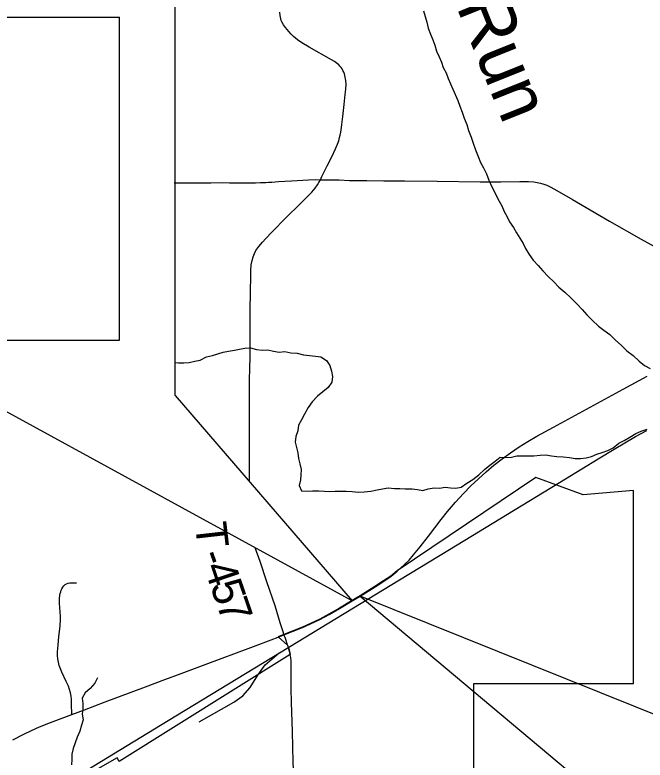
# Model space of a CAD drawing. Extents: x 0 to 34, y 0 to 22.
# Drawn here: x 4.117 to 5.253, y 16.828 to 18.172 of the extents above; entities that cross this region are included whole.
import ezdxf

# ---------------------------------------------------------------- set-up
doc = ezdxf.new("R2010")
doc.units = 0
for name, color, linetype in [('GM_X_County_Road', 7, 'Continuous'), ('GM_X_County_Road_Text', 7, 'Continuous'), ('GM_X_County_Text', 7, 'Continuous'), ('GM_X_Interchange_Ramps', 7, 'Continuous'), ('GM_X_State_Route', 7, 'Continuous'), ('GM_X_Township_Road_Text', 7, 'Continuous'), ('GM_X_Township_Text', 7, 'Continuous'), ('SH_Text', 7, 'Continuous')]:
    doc.layers.add(name, color=color, linetype=linetype)

msp = doc.modelspace()

# ---------------------------------------------------------------- linework, layer by layer
at = {"layer": 'GM_X_County_Road'}
for points in [[(4.8065, 17.1688), (4.8197, 17.1807), (4.8277, 17.1889), (4.836, 17.1981), (4.8477, 17.2126), (4.8629, 17.2322), (4.8854, 17.262), (4.8971, 17.2766), (4.9113, 17.2931), (4.926, 17.3091), (4.9391, 17.3225), (4.9527, 17.3353), (4.9666, 17.3478), (4.9809, 17.3598), (4.9956, 17.3713), (5.0107, 17.3823), (5.0261, 17.3928), (5.0419, 17.4028), (5.058, 17.4123), (5.088, 17.4288), (5.2137, 17.4969), (5.2573, 17.5207)], [(4.5916, 17.05), (4.6021, 17.0542), (4.6357, 17.0673), (4.65, 17.0736), (4.6668, 17.0818), (4.6834, 17.0905), (4.7023, 17.1014), (4.7253, 17.1152), (4.7398, 17.1239), (4.7664, 17.1403), (4.7821, 17.1505), (4.7949, 17.1595), (4.7989, 17.1626), (4.8065, 17.1688)], [(4.1131, 16.8647), (4.1328, 16.8749), (4.1468, 16.8816), (4.1611, 16.8878), (4.1813, 16.8958), (4.2194, 16.9103), (4.2422, 16.9189), (4.2799, 16.9331), (4.3525, 16.9603), (4.3874, 16.9733), (4.4164, 16.9843), (4.46, 17.0006), (4.5471, 17.0332), (4.5791, 17.0452), (4.5916, 17.05)]]:
    msp.add_lwpolyline(points, dxfattribs=at)
at = {"layer": 'GM_X_County_Road_Text'}
for points in [[(4.8535, 18.1796), (4.8568, 18.1693), (4.8597, 18.159), (4.8623, 18.148), (4.8664, 18.1374), (4.8708, 18.1271), (4.8742, 18.1172), (4.8771, 18.1065), (4.882, 18.0963), (4.8864, 18.0867), (4.8894, 18.0772), (4.8946, 18.0673), (4.8983, 18.0571), (4.9065, 18.038), (4.9154, 18.0175), (4.9195, 18.0076), (4.9236, 17.9965), (4.9269, 17.9855), (4.9321, 17.9741), (4.9347, 17.9634), (4.9399, 17.9513), (4.9436, 17.9406), (4.9477, 17.9288), (4.9521, 17.9166), (4.9566, 17.9056), (4.9618, 17.8961), (4.9674, 17.8854), (4.9718, 17.874), (4.9771, 17.8618), (4.9823, 17.8519), (4.9879, 17.8405), (4.995, 17.8275), (4.9994, 17.8176), (5.0047, 17.8081), (5.0091, 17.7986), (5.0159, 17.7886), (5.0215, 17.7791), (5.0278, 17.7696), (5.0338, 17.76), (5.0379, 17.7505), (5.0443, 17.7398), (5.0514, 17.7295), (5.0608, 17.72), (5.069, 17.7104), (5.0788, 17.7005), (5.0886, 17.6909)], [(5.0886, 17.6909), (5.0976, 17.681), (5.1085, 17.6721), (5.1198, 17.6614), (5.1311, 17.6503), (5.1401, 17.6408), (5.1484, 17.6308), (5.1581, 17.6213), (5.1694, 17.6109), (5.1792, 17.6036), (5.1901, 17.5956), (5.2003, 17.5852), (5.2101, 17.5764), (5.2206, 17.5661), (5.2319, 17.5576), (5.2428, 17.5477), (5.2526, 17.54), (5.2624, 17.5342)], [(4.4056, 17.5451), (4.4119, 17.5446), (4.4214, 17.5445), (4.4309, 17.5452), (4.4412, 17.5477), (4.451, 17.5495), (4.4621, 17.5551), (4.4731, 17.558), (4.483, 17.561), (4.4925, 17.5636), (4.5023, 17.5654), (4.5126, 17.5672), (4.5221, 17.5694), (4.5316, 17.5712), (4.5418, 17.5715), (4.5528, 17.5687), (4.563, 17.5675), (4.5732, 17.5678), (4.5831, 17.5658), (4.5933, 17.5638), (4.6039, 17.5648), (4.6145, 17.5625), (4.6262, 17.562), (4.6376, 17.5588), (4.6482, 17.558), (4.6588, 17.5564), (4.6686, 17.5551), (4.6788, 17.549), (4.6848, 17.5395), (4.6881, 17.5292), (4.6899, 17.5197), (4.6883, 17.5098), (4.6818, 17.5), (4.6719, 17.4925), (4.6624, 17.4843), (4.6532, 17.4741), (4.6459, 17.464), (4.639, 17.4519), (4.6336, 17.4417), (4.6286, 17.4319), (4.627, 17.422), (4.6235, 17.4118), (4.6223, 17.4016), (4.6248, 17.3917), (4.627, 17.3822), (4.6281, 17.3723), (4.631, 17.3625), (4.6332, 17.3522), (4.6328, 17.3427), (4.6319, 17.3333), (4.6296, 17.3234), (4.634, 17.3139), (4.6443, 17.313), (4.6538, 17.3137), (4.6651, 17.3136), (4.675, 17.3131), (4.6844, 17.3127), (4.6947, 17.313), (4.7144, 17.3128), (4.7254, 17.3123), (4.736, 17.3111), (4.7466, 17.3121), (4.7587, 17.3128), (4.7701, 17.3153), (4.7796, 17.3171), (4.7902, 17.3189), (4.8016, 17.3181), (4.8111, 17.318), (4.8206, 17.3175), (4.8331, 17.3174), (4.8429, 17.3162), (4.8527, 17.3142), (4.8622, 17.3171)], [(4.8622, 17.3171), (4.8729, 17.3193), (4.8827, 17.3185), (4.8926, 17.3203), (4.9024, 17.3191), (4.9119, 17.3186), (4.9214, 17.3204), (4.9317, 17.3275), (4.9427, 17.3339), (4.9538, 17.3425), (4.9637, 17.3522), (4.9733, 17.3601), (4.9828, 17.3672), (4.9923, 17.3747), (5.0026, 17.3739), (5.0124, 17.3746), (5.0219, 17.3767), (5.0322, 17.3767), (5.0435, 17.3769), (5.053, 17.3768), (5.0644, 17.3783), (5.0746, 17.3789), (5.0845, 17.3769), (5.0943, 17.3757), (5.1057, 17.3752), (5.117, 17.374), (5.1273, 17.372), (5.1371, 17.3719), (5.147, 17.3733), (5.1569, 17.3755), (5.1664, 17.3796), (5.1759, 17.3826), (5.1861, 17.3866), (5.196, 17.3911), (5.2059, 17.3994), (5.2155, 17.4042), (5.2257, 17.4102), (5.2368, 17.4173), (5.2463, 17.4214), (5.2569, 17.4247)], [(4.2659, 16.9767), (4.2609, 16.9669), (4.2528, 16.9571), (4.2433, 16.9496), (4.2379, 16.9398), (4.2393, 16.9303), (4.2393, 16.9208), (4.2384, 16.9109), (4.2398, 16.9007), (4.2367, 16.8909), (4.234, 16.8803), (4.2294, 16.8697), (4.2255, 16.8595), (4.2216, 16.8489), (4.2192, 16.8391), (4.2192, 16.8292), (4.2191, 16.8197)]]:
    msp.add_lwpolyline(points, dxfattribs=at)
at = {"layer": 'GM_X_County_Text'}
for points in [[(4.185, 16.7727), (4.3934, 16.8994), (4.6106, 17.0317), (4.8107, 17.1533), (4.9005, 17.208), (5.1096, 17.3353), (5.1688, 17.3712), (5.1978, 17.3889), (5.236, 17.4114), (5.2564, 17.4226)], [(4.4493, 16.8974), (4.5114, 16.9327), (4.5279, 16.9439), (4.5413, 16.9589), (4.5548, 16.9814), (4.5682, 17.0001), (4.5935, 17.0213)]]:
    msp.add_lwpolyline(points, dxfattribs=at)
at = {"layer": 'GM_X_Interchange_Ramps'}
for points in [[(4.668, 17.8748), (4.6706, 17.8803), (4.6737, 17.8868), (4.6801, 17.8996), (4.6887, 17.9162), (4.6952, 17.9303), (4.6988, 17.9389), (4.7008, 17.9449), (4.7024, 17.951), (4.7034, 17.9549), (4.7044, 17.9603), (4.7057, 17.9691), (4.7063, 17.9743), (4.708, 17.9889), (4.7104, 18.0105), (4.7126, 18.0286), (4.7136, 18.0379), (4.714, 18.0473), (4.7137, 18.0536), (4.7127, 18.0599), (4.712, 18.063), (4.7111, 18.066), (4.7099, 18.0689), (4.7084, 18.0718), (4.7068, 18.0745), (4.705, 18.0771), (4.703, 18.0795), (4.7008, 18.0818), (4.6984, 18.0839), (4.6934, 18.0877), (4.6881, 18.0911), (4.6473, 18.1139), (4.6341, 18.1219), (4.6265, 18.1272), (4.6193, 18.133), (4.6149, 18.1373), (4.6107, 18.1418), (4.6049, 18.149), (4.6014, 18.1541), (4.5984, 18.1594), (4.5973, 18.1621), (4.5963, 18.1647), (4.5956, 18.168), (4.5951, 18.171), (4.5945, 18.1771)], [(4.5397, 17.3302), (4.5398, 17.3387), (4.5399, 17.3625), (4.5399, 17.4012), (4.5399, 17.4851), (4.5402, 17.5126), (4.5406, 17.5354), (4.5409, 17.5541), (4.5409, 17.5649), (4.5409, 17.5958), (4.5413, 17.6349), (4.5416, 17.676), (4.5421, 17.6976), (4.5424, 17.7109), (4.5432, 17.7211), (4.5448, 17.7288), (4.5466, 17.7356), (4.5488, 17.7418), (4.5515, 17.747), (4.5568, 17.7545), (4.5634, 17.7619), (4.5694, 17.769), (4.58, 17.7803), (4.6063, 17.8067), (4.6306, 17.8307), (4.6439, 17.8437), (4.6524, 17.8526), (4.6584, 17.8598), (4.6626, 17.8658), (4.665, 17.8697), (4.668, 17.8748)], [(4.5741, 17.8701), (4.5801, 17.8705), (4.5921, 17.8713), (4.6039, 17.8722), (4.6154, 17.873), (4.6461, 17.8744), (4.6584, 17.8749), (4.668, 17.8748)], [(4.668, 17.8748), (4.6729, 17.8748), (4.6841, 17.8746), (4.7014, 17.8743), (4.7202, 17.8736), (4.7242, 17.8736)], [(4.7242, 17.8736), (4.7513, 17.8735), (4.7823, 17.8729), (4.8196, 17.8727), (4.8786, 17.872), (4.9562, 17.8712), (4.9935, 17.8711), (5.0277, 17.8715), (5.0432, 17.8713), (5.0525, 17.8708), (5.0586, 17.87), (5.0647, 17.8687), (5.0707, 17.867), (5.0764, 17.8647), (5.082, 17.862), (5.0902, 17.8576), (5.1225, 17.8389), (5.1544, 17.8202), (5.1895, 17.8002), (5.2461, 17.7678), (5.2814, 17.7482), (5.2916, 17.7428)], [(4.4043, 17.8692), (4.4234, 17.8693), (4.4452, 17.8693), (4.47, 17.8694), (4.4917, 17.8695), (4.5041, 17.8693), (4.5288, 17.8693), (4.5412, 17.8693), (4.5505, 17.8694), (4.5598, 17.8695), (4.5691, 17.8698), (4.5741, 17.8701)], [(4.6021, 17.0542), (4.601, 17.0578), (4.5952, 17.0758), (4.586, 17.1063), (4.5714, 17.1495), (4.5592, 17.1862), (4.5499, 17.211)], [(4.2194, 16.9103), (4.2192, 16.9153), (4.2189, 16.9246), (4.2186, 16.9371), (4.218, 16.9433), (4.2169, 16.9495), (4.2154, 16.9555), (4.2132, 16.9614), (4.2094, 16.9699), (4.2013, 16.9868), (4.1989, 16.9926), (4.1968, 16.9985), (4.1953, 17.0045), (4.1943, 17.0107), (4.1938, 17.0169), (4.1939, 17.0231), (4.1948, 17.0356), (4.1963, 17.0511), (4.1982, 17.0697), (4.1992, 17.0821), (4.1992, 17.0883), (4.1987, 17.0944), (4.1976, 17.1036), (4.1973, 17.1098), (4.1974, 17.1192), (4.198, 17.1253), (4.1986, 17.1284), (4.1994, 17.1314), (4.2004, 17.1344), (4.2017, 17.1372), (4.2032, 17.1399), (4.2051, 17.1424), (4.2073, 17.1445), (4.2099, 17.1461), (4.2128, 17.1471), (4.2159, 17.1476), (4.2189, 17.1478), (4.222, 17.1478), (4.2277, 17.1477)], [(4.6086, 17.0356), (4.6059, 17.0436), (4.604, 17.0489), (4.6021, 17.0542)], [(4.6135, 17.018), (4.6132, 17.0199), (4.6115, 17.0263), (4.6089, 17.0347), (4.6086, 17.0356)], [(4.6214, 16.732), (4.6214, 16.733), (4.6213, 16.7361), (4.6212, 16.741), (4.6211, 16.7443), (4.621, 16.7494), (4.6209, 16.7541), (4.621, 16.7567), (4.621, 16.7599), (4.6207, 16.7628), (4.6206, 16.7658), (4.6205, 16.7719), (4.6202, 16.7874), (4.6189, 16.8245), (4.6172, 16.8799), (4.6156, 16.9322), (4.6153, 16.9575), (4.6153, 16.9681), (4.6153, 16.9872), (4.6153, 16.9997), (4.6151, 17.0071), (4.6145, 17.0131), (4.6135, 17.018)]]:
    msp.add_lwpolyline(points, dxfattribs=at)
at = {"layer": 'GM_X_State_Route'}
msp.add_lwpolyline([(4.9445, 16.7008), (4.9445, 16.966), (5.2324, 16.966), (5.2325, 17.3145), (5.1419, 17.3066), (5.0565, 17.3377), (4.8063, 17.1693), (4.7987, 17.1631), (4.7946, 17.1601), (4.7819, 17.1511), (4.7662, 17.1409), (4.7396, 17.1245), (4.7251, 17.1157), (4.7021, 17.1019), (4.6832, 17.091), (4.6666, 17.0823), (4.6498, 17.0742), (4.6355, 17.0678), (4.6019, 17.0547), (4.5914, 17.0506), (4.6087, 17.0352), (4.6113, 17.0268), (4.6133, 17.0186), (4.3049, 16.8256), (4.3011, 16.8324), (4.1149, 16.7255)], dxfattribs=at)
at = {"layer": 'SH_Text'}
for p, q in [((4.4056, 17.4855), (4.4056, 18.2679)), ((2.1719, 18.1679), (4.3056, 18.1679)), ((4.3056, 17.5855), (4.3056, 18.1679)), ((2.1719, 17.5855), (4.3056, 17.5855))]:
    msp.add_line(p, q, dxfattribs=at)
for points in [[(4.4056, 17.4855), (4.7253, 17.1152), (4.0477, 17.4855)], [(5.4199, 16.8504), (4.7398, 17.1239), (5.4199, 16.5526)]]:
    msp.add_lwpolyline(points, dxfattribs=at)

# ---------------------------------------------------------------- texts
at = {"layer": 'GM_X_Township_Road_Text'}
msp.add_text('Run', height=0.09472, rotation=291.8808, dxfattribs=at).set_placement((4.9124, 18.1875))
at = {"layer": 'GM_X_Township_Text'}
for s, rotation, p in [('T', 276.5499, (4.4414, 17.2542)), ('-', 289.4897, (4.4494, 17.1984)), ('4', 288.7723, (4.4571, 17.1765)), ('5', 288.9538, (4.4684, 17.1432)), ('7', 288.9875, (4.4798, 17.1101))]:
    msp.add_text(s, height=0.0568, rotation=rotation, dxfattribs=at).set_placement(p)

doc.saveas('drawing.dxf')
